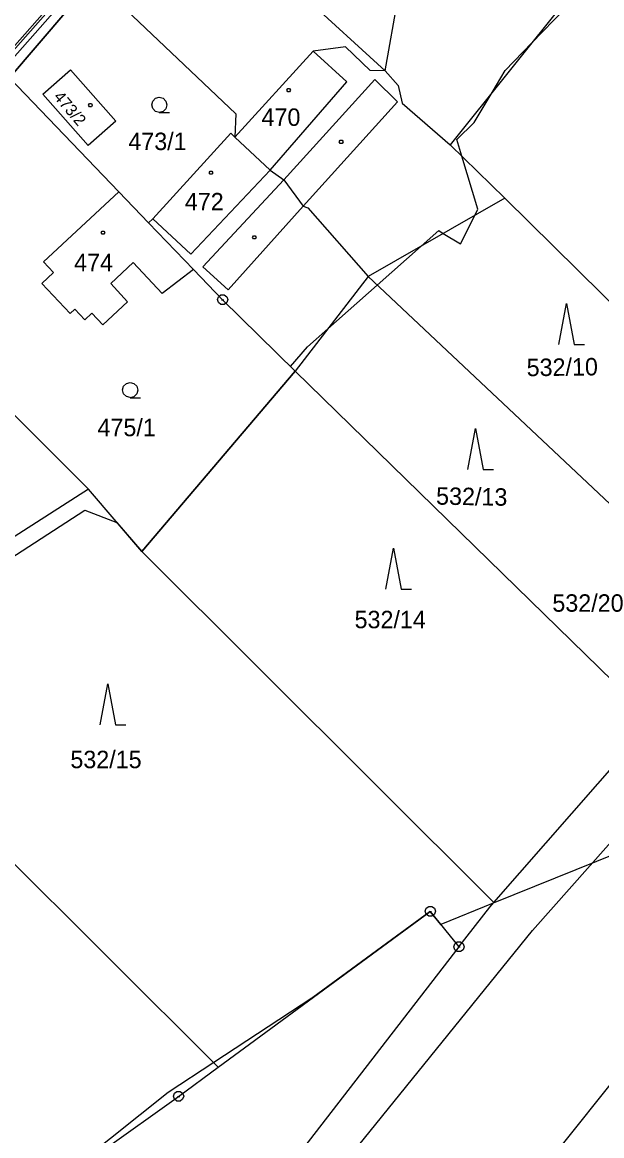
# Model space of a CAD drawing. Extents: x -759699 to -757730, y -1172308 to -1170857.
# Drawn here: x -759435.7 to -759379.2, y -1171819.8 to -1171711.2 of the extents above; entities that cross this region are included whole.
import ezdxf

# ---------------------------------------------------------------- set-up
doc = ezdxf.new("R2010")
doc.units = 0
for name, color, linetype in [('Vrstva 1', 7, 'Continuous'), ('Vrstva 11', 7, 'Continuous'), ('Vrstva 12', 7, 'Continuous'), ('Vrstva 13', 7, 'Continuous'), ('Vrstva 2', 7, 'Continuous'), ('Vrstva 3', 7, 'Continuous'), ('Vrstva 4', 7, 'Continuous'), ('Vrstva 5', 7, 'Continuous'), ('Vrstva 7', 7, 'Continuous'), ('Vrstva 8', 7, 'Continuous')]:
    doc.layers.add(name, color=color, linetype=linetype)

msp = doc.modelspace()

# ---------------------------------------------------------------- linework, layer by layer
at = {"layer": 'Vrstva 1'}
for p, q in [((-759420.41, -1171697.55), (-759400.3, -1171715.91)), ((-759400.3, -1171715.91), (-759398.64, -1171706.59)), ((-759380.05, -1171705.77), (-759393.97, -1171723.12)), ((-759428.63, -1171707.06), (-759414.89, -1171720.1)), ((-759436.98, -1171716.58), (-759431.38, -1171710.06)), ((-759407.33, -1171713.98), (-759414.97, -1171722.38)), ((-759404.19, -1171713.57), (-759407.33, -1171713.98)), ((-759401.78, -1171715.88), (-759404.19, -1171713.57)), ((-759433.71, -1171718.18), (-759431.03, -1171715.8)), ((-759431.03, -1171715.8), (-759426.59, -1171720.81)), ((-759400.3, -1171715.91), (-759401.78, -1171715.88)), ((-759400.3, -1171715.91), (-759399.03, -1171717.33)), ((-759426.3, -1171727.72), (-759436.98, -1171716.58)), ((-759399.03, -1171717.33), (-759398.66, -1171719.07)), ((-759429.28, -1171723.19), (-759433.71, -1171718.18)), ((-759398.66, -1171719.07), (-759393.97, -1171723.12)), ((-759426.59, -1171720.81), (-759429.28, -1171723.19)), ((-759414.89, -1171720.1), (-759414.97, -1171722.38)), ((-759415.37, -1171722), (-759422.99, -1171730.34)), ((-759415.37, -1171722), (-759414.97, -1171722.38)), ((-759414.97, -1171722.38), (-759411.54, -1171725.59)), ((-759393.97, -1171723.12), (-759388.62, -1171728.34)), ((-759411.54, -1171725.59), (-759410.21, -1171726.54)), ((-759410.21, -1171726.54), (-759408.32, -1171729.1)), ((-759433.65, -1171734.53), (-759426.3, -1171727.72)), ((-759423.41, -1171730.73), (-759426.3, -1171727.72)), ((-759388.62, -1171728.34), (-759401.97, -1171735.98)), ((-759388.62, -1171728.34), (-759363.28, -1171753.33)), ((-759408.32, -1171729.1), (-759407.87, -1171729.28)), ((-759407.87, -1171729.28), (-759401.97, -1171735.98)), ((-759422.99, -1171730.34), (-759423.41, -1171730.73)), ((-759423.41, -1171730.73), (-759419.02, -1171735.28)), ((-759432.67, -1171735.58), (-759433.65, -1171734.53)), ((-759424.9, -1171734.61), (-759427.09, -1171736.65)), ((-759422.06, -1171737.63), (-759424.9, -1171734.61)), ((-759433.81, -1171736.65), (-759432.67, -1171735.58)), ((-759419.02, -1171735.28), (-759422.06, -1171737.63)), ((-759419.02, -1171735.28), (-759416.17, -1171738.24)), ((-759401.97, -1171735.98), (-759409.08, -1171745.22)), ((-759401.97, -1171735.98), (-759370.13, -1171765.9)), ((-759431.04, -1171739.57), (-759433.81, -1171736.65)), ((-759427.09, -1171736.65), (-759425.44, -1171738.45)), ((-759416.17, -1171738.24), (-759409.08, -1171745.22)), ((-759430.59, -1171739.15), (-759431.04, -1171739.57)), ((-759429.61, -1171740.2), (-759430.59, -1171739.15)), ((-759425.44, -1171738.45), (-759427.85, -1171740.68)), ((-759428.93, -1171739.56), (-759429.61, -1171740.2)), ((-759427.85, -1171740.68), (-759428.93, -1171739.56)), ((-759409.08, -1171745.22), (-759424.05, -1171762.8)), ((-759409.08, -1171745.22), (-759373.94, -1171779.5)), ((-759438.83, -1171747.15), (-759429.27, -1171756.73)), ((-759429.27, -1171756.73), (-759456.21, -1171773.94)), ((-759424.05, -1171762.8), (-759429.27, -1171756.73)), ((-759424.05, -1171762.8), (-759389.71, -1171797.04)), ((-759389.71, -1171797.04), (-759377.02, -1171782.55)), ((-759439.54, -1171790.25), (-759416.59, -1171813.09)), ((-759416.59, -1171813.09), (-759395.9, -1171797.9)), ((-759395.9, -1171797.9), (-759393.11, -1171801.36)), ((-759393.11, -1171801.36), (-759390.1, -1171797.48)), ((-759390.1, -1171797.48), (-759389.71, -1171797.04)), ((-759393.11, -1171801.36), (-759428.04, -1171846.47)), ((-759420.47, -1171815.94), (-759416.59, -1171813.09)), ((-759427.86, -1171821.23), (-759420.47, -1171815.94))]:
    msp.add_line(p, q, dxfattribs=at)
at = {"layer": 'Vrstva 11'}
for p, q in [((-759386, -1171713.19), (-759380.07, -1171707.06)), ((-759388.61, -1171715.88), (-759386, -1171713.19)), ((-759389.88, -1171718.02), (-759388.61, -1171715.88)), ((-759391.61, -1171720.94), (-759389.88, -1171718.02)), ((-759393.32, -1171722.62), (-759391.61, -1171720.94)), ((-759392.83, -1171724.23), (-759393.32, -1171722.62)), ((-759391.25, -1171729.42), (-759392.83, -1171724.23)), ((-759391.55, -1171730.02), (-759391.25, -1171729.42)), ((-759392.96, -1171732.79), (-759391.55, -1171730.02)), ((-759396.78, -1171733.01), (-759395.08, -1171731.5)), ((-759395.08, -1171731.5), (-759394.63, -1171731.78)), ((-759394.63, -1171731.78), (-759392.96, -1171732.79)), ((-759401.08, -1171736.82), (-759396.78, -1171733.01)), ((-759405.89, -1171741.07), (-759401.08, -1171736.82)), ((-759407.88, -1171742.83), (-759405.89, -1171741.07)), ((-759409.54, -1171744.76), (-759407.88, -1171742.83)), ((-759409.08, -1171745.22), (-759409.54, -1171744.76)), ((-759424.05, -1171762.8), (-759409.08, -1171745.22)), ((-759450.91, -1171772.55), (-759429.61, -1171758.75)), ((-759429.61, -1171758.75), (-759426.48, -1171759.98)), ((-759426.48, -1171759.98), (-759424.05, -1171762.8)), ((-759377.66, -1171792.21), (-759389.77, -1171797.1)), ((-759395.9, -1171797.9), (-759407.35, -1171806.3)), ((-759394.88, -1171799.17), (-759395.9, -1171797.9)), ((-759389.77, -1171797.1), (-759394.88, -1171799.17)), ((-759407.45, -1171806.36), (-759417.04, -1171812.64)), ((-759407.35, -1171806.3), (-759407.45, -1171806.36)), ((-759417.04, -1171812.64), (-759421.5, -1171815.56)), ((-759421.5, -1171815.56), (-759435.19, -1171826.48))]:
    msp.add_line(p, q, dxfattribs=at)
at = {"layer": 'Vrstva 12'}
for p, q in [((-759407.33, -1171713.98), (-759414.97, -1171722.38)), ((-759404.05, -1171716.98), (-759407.33, -1171713.98)), ((-759433.71, -1171718.18), (-759431.03, -1171715.8)), ((-759431.03, -1171715.8), (-759426.59, -1171720.81)), ((-759411.54, -1171725.59), (-759404.05, -1171716.98)), ((-759429.28, -1171723.19), (-759433.71, -1171718.18)), ((-759426.59, -1171720.81), (-759429.28, -1171723.19)), ((-759415.37, -1171722), (-759422.99, -1171730.34)), ((-759415.37, -1171722), (-759414.97, -1171722.38)), ((-759414.97, -1171722.38), (-759411.54, -1171725.59)), ((-759414.97, -1171722.38), (-759411.54, -1171725.59)), ((-759419.26, -1171733.79), (-759411.54, -1171725.59)), ((-759433.65, -1171734.53), (-759426.3, -1171727.72)), ((-759423.41, -1171730.73), (-759426.3, -1171727.72)), ((-759422.99, -1171730.34), (-759419.26, -1171733.79)), ((-759423.41, -1171730.73), (-759419.02, -1171735.28)), ((-759432.67, -1171735.58), (-759433.65, -1171734.53)), ((-759424.9, -1171734.61), (-759427.09, -1171736.65)), ((-759422.06, -1171737.63), (-759424.9, -1171734.61)), ((-759433.81, -1171736.65), (-759432.67, -1171735.58)), ((-759419.02, -1171735.28), (-759422.06, -1171737.63)), ((-759431.04, -1171739.57), (-759433.81, -1171736.65)), ((-759427.09, -1171736.65), (-759425.44, -1171738.45)), ((-759430.59, -1171739.15), (-759431.04, -1171739.57)), ((-759429.61, -1171740.2), (-759430.59, -1171739.15)), ((-759425.44, -1171738.45), (-759427.85, -1171740.68)), ((-759428.93, -1171739.56), (-759429.61, -1171740.2)), ((-759427.85, -1171740.68), (-759428.93, -1171739.56))]:
    msp.add_line(p, q, dxfattribs=at)
at = {"layer": 'Vrstva 13'}
for p, q in [((-759437.42, -1171714.55), (-759429.1, -1171705.11)), ((-759441.11, -1171718.97), (-759432.23, -1171708.97)), ((-759432.02, -1171709.49), (-759440.58, -1171719.13)), ((-759431.38, -1171710.06), (-759436.98, -1171716.58))]:
    msp.add_line(p, q, dxfattribs=at)
at = {"layer": 'Vrstva 3'}
for points in [[(-759422.34, -1171719.97), (-759422.72, -1171719.87), (-759422.99, -1171719.6), (-759423.09, -1171719.23), (-759422.99, -1171718.86), (-759422.72, -1171718.59), (-759422.35, -1171718.49), (-759421.98, -1171718.59), (-759421.71, -1171718.86), (-759421.61, -1171719.24), (-759421.71, -1171719.62), (-759421.98, -1171719.89), (-759422.36, -1171719.99), (-759421.36, -1171719.99)], [(-759383.35, -1171742.61), (-759382.6, -1171738.61), (-759381.85, -1171742.61), (-759380.85, -1171742.61)], [(-759425.18, -1171747.78), (-759425.56, -1171747.68), (-759425.83, -1171747.41), (-759425.93, -1171747.04), (-759425.83, -1171746.67), (-759425.56, -1171746.4), (-759425.19, -1171746.3), (-759424.82, -1171746.4), (-759424.55, -1171746.67), (-759424.45, -1171747.05), (-759424.55, -1171747.43), (-759424.82, -1171747.7), (-759425.2, -1171747.8), (-759424.2, -1171747.8)], [(-759392.24, -1171754.79), (-759391.49, -1171750.79), (-759390.74, -1171754.79), (-759389.74, -1171754.79)], [(-759400.25, -1171766.46), (-759399.5, -1171762.46), (-759398.75, -1171766.46), (-759397.75, -1171766.46)], [(-759428.11, -1171779.71), (-759427.36, -1171775.71), (-759426.61, -1171779.71), (-759425.61, -1171779.71)]]:
    msp.add_lwpolyline(points, dxfattribs=at)
at = {"layer": 'Vrstva 4'}
for p, q in [((-759404.05, -1171716.98), (-759407.33, -1171713.98)), ((-759411.54, -1171725.59), (-759404.05, -1171716.98)), ((-759410.21, -1171726.54), (-759401.3, -1171716.76)), ((-759401.3, -1171716.76), (-759399.11, -1171718.94)), ((-759399.11, -1171718.94), (-759408.32, -1171729.1)), ((-759419.26, -1171733.79), (-759411.54, -1171725.59)), ((-759410.21, -1171726.54), (-759418.1, -1171735.03)), ((-759415.63, -1171737.26), (-759408.32, -1171729.1)), ((-759422.99, -1171730.34), (-759419.26, -1171733.79)), ((-759418.1, -1171735.03), (-759415.63, -1171737.26)), ((-759385.94, -1171799.75), (-759365.17, -1171776.39)), ((-759411.6, -1171831.44), (-759385.94, -1171799.75)), ((-759373.92, -1171809.21), (-759399.11, -1171840.79))]:
    msp.add_line(p, q, dxfattribs=at)
at = {"layer": 'Vrstva 5'}
for points in [[(-759409.64, -1171717.65), (-759409.55, -1171717.8), (-759409.64, -1171717.95), (-759409.82, -1171717.95), (-759409.91, -1171717.8), (-759409.82, -1171717.65)], [(-759428.98, -1171719.11), (-759428.89, -1171719.26), (-759428.98, -1171719.41), (-759429.16, -1171719.41), (-759429.25, -1171719.26), (-759429.16, -1171719.11)], [(-759404.51, -1171722.69), (-759404.42, -1171722.84), (-759404.51, -1171722.99), (-759404.69, -1171722.99), (-759404.78, -1171722.84), (-759404.69, -1171722.69)], [(-759417.21, -1171725.7), (-759417.12, -1171725.85), (-759417.21, -1171726), (-759417.39, -1171726), (-759417.48, -1171725.85), (-759417.39, -1171725.7)], [(-759427.75, -1171731.54), (-759427.66, -1171731.69), (-759427.75, -1171731.84), (-759427.93, -1171731.84), (-759428.02, -1171731.69), (-759427.93, -1171731.54)], [(-759412.98, -1171732.01), (-759412.89, -1171732.16), (-759412.98, -1171732.31), (-759413.16, -1171732.31), (-759413.25, -1171732.16), (-759413.16, -1171732.01)]]:
    msp.add_lwpolyline(points, close=True, dxfattribs=at)
at = {"layer": 'Vrstva 8'}
for p, q in [((-759416.29, -1171738.24), (-759416.05, -1171738.24)), ((-759396.02, -1171797.9), (-759395.78, -1171797.9)), ((-759393.23, -1171801.36), (-759392.99, -1171801.36)), ((-759420.59, -1171815.94), (-759420.35, -1171815.94))]:
    msp.add_line(p, q, dxfattribs=at)
for points in [[(-759416.02, -1171737.76), (-759415.77, -1171737.94), (-759415.67, -1171738.23), (-759415.77, -1171738.52), (-759416.02, -1171738.7), (-759416.33, -1171738.7), (-759416.58, -1171738.52), (-759416.68, -1171738.23), (-759416.58, -1171737.94), (-759416.33, -1171737.76)], [(-759395.75, -1171797.42), (-759395.5, -1171797.6), (-759395.4, -1171797.89), (-759395.5, -1171798.18), (-759395.75, -1171798.36), (-759396.06, -1171798.36), (-759396.31, -1171798.18), (-759396.41, -1171797.89), (-759396.31, -1171797.6), (-759396.06, -1171797.42)], [(-759392.96, -1171800.88), (-759392.71, -1171801.06), (-759392.61, -1171801.35), (-759392.71, -1171801.64), (-759392.96, -1171801.82), (-759393.27, -1171801.82), (-759393.52, -1171801.64), (-759393.62, -1171801.35), (-759393.52, -1171801.06), (-759393.27, -1171800.88)], [(-759420.32, -1171815.46), (-759420.07, -1171815.64), (-759419.97, -1171815.93), (-759420.07, -1171816.22), (-759420.32, -1171816.4), (-759420.63, -1171816.4), (-759420.88, -1171816.22), (-759420.98, -1171815.93), (-759420.88, -1171815.64), (-759420.63, -1171815.46)]]:
    msp.add_lwpolyline(points, close=True, dxfattribs=at)

# ---------------------------------------------------------------- texts
at = {"layer": 'Vrstva 2'}
for s, height, rotation, p in [('473/2', 1.14, 310.31394, (-759432.732, -1171718.483)), ('532/10', 1.7, 0.74484, (-759386.488, -1171745.702)), ('532/13', 1.7, 359.01536, (-759395.348, -1171758.22))]:
    msp.add_text(s, height=height, rotation=rotation, dxfattribs=at).set_placement(p)
for s, p in [('470', (-759412.371, -1171721.28)), ('473/1', (-759425.372, -1171723.64)), ('472', (-759419.858, -1171729.52)), ('474', (-759430.664, -1171735.46)), ('475/1', (-759428.382, -1171751.55)), ('532/14', (-759403.292, -1171770.28)), ('532/15', (-759431.029, -1171783.93))]:
    msp.add_text(s, height=1.7, dxfattribs=at).set_placement(p)
at = {"layer": 'Vrstva 7'}
msp.add_text('532/20', height=1.7, dxfattribs=at).set_placement((-759383.989, -1171768.67))

doc.saveas('drawing.dxf')
